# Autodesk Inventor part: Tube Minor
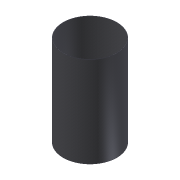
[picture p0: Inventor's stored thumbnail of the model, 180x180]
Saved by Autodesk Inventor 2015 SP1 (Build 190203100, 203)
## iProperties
Category: Mechanical Engineering Drawing and Design - CADD
Manager: Fábio Ricardo de Oliveira Souza
Company: SENAI - Serviço Nacional de Aprendizagem Industrial
Created: 2011-06
Part Number: Tube Minor
Material: Steel
Description: Stainless Steel (DIN- X6CrNiTi18-10)
Document SubType Name: Modeling
Designer: Guilherme Augusto Franco de Souza
Engineer: George Geraldo de Oliveia Silva
Authority: Fábio Ricardo de Oliveira Soza
Density: 7.85 g/cm^3
Mass: 906.31 g
Surface Area: 2318.31 cm^2
Volume: 115.454 cm^3
Appearance: Machined 02
Subject: WorldSkill 2011 - London, England
Author: Guilherme Augusto Franco de Souza
Revision Number: 00
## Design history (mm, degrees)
derived "Tube.ipt"
body "Solid2"
feature "Solid2::Tube.ipt"
tag "TaggingFeature1"
other parameters: "d6" = 25, "d7" = 125, "d9" = 0, "d11" = 90 deg, "Diam_ext" = 148, "d4" = 0, "d5" = 1
